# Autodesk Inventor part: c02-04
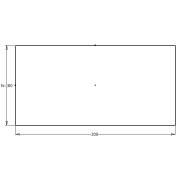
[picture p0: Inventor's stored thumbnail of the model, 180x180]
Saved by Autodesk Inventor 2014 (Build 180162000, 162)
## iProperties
Created: 2013-02
Part Number: c02-04
Material: Generic
Document SubType Name: Modeling
Designer: Thom Tremblay
Density: 1 g/cm^3
Appearance: Default
Author: Thom Tremblay
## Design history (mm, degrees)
sketch "Sketch1"
  geometry: L1 (100, -50)-(100, 50); L2 (100, 50)-(-100, 50); L3 (-100, 50)-(-100, -50); L4 (-100, -50)-(100, -50); 3 further points
  constraints: 8 end point, 2 midpoint, 1 horizontal, 1 horizontal alignment, 1 parallel, 1 perpendicular, 1 vertical, 1 vertical alignment
  dimensions: "d0" = 200 dimension on point (0, 0) L1.end L1 L2.end L2 L3.end L3 L1.start L4 point (-100, 0) point (0, 50); "d0" = 200 distance of L3.end L1.start; "Height" = 100 distance of L2.end L3.end (= 0.5 x d0)
